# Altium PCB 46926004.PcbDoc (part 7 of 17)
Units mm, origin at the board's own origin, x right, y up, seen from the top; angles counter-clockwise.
Board outline 250 x 200 mm, 6 copper layers (Top Layer, INT1_GND, INT2_SIG, INT3_SIG, INT4_GND, Bottom Layer), stack 1.71 mm thick; 1450 components, 1293 nets, 5656 pads, 2307 vias.
Unrouted connection lines stored in the file: 2.
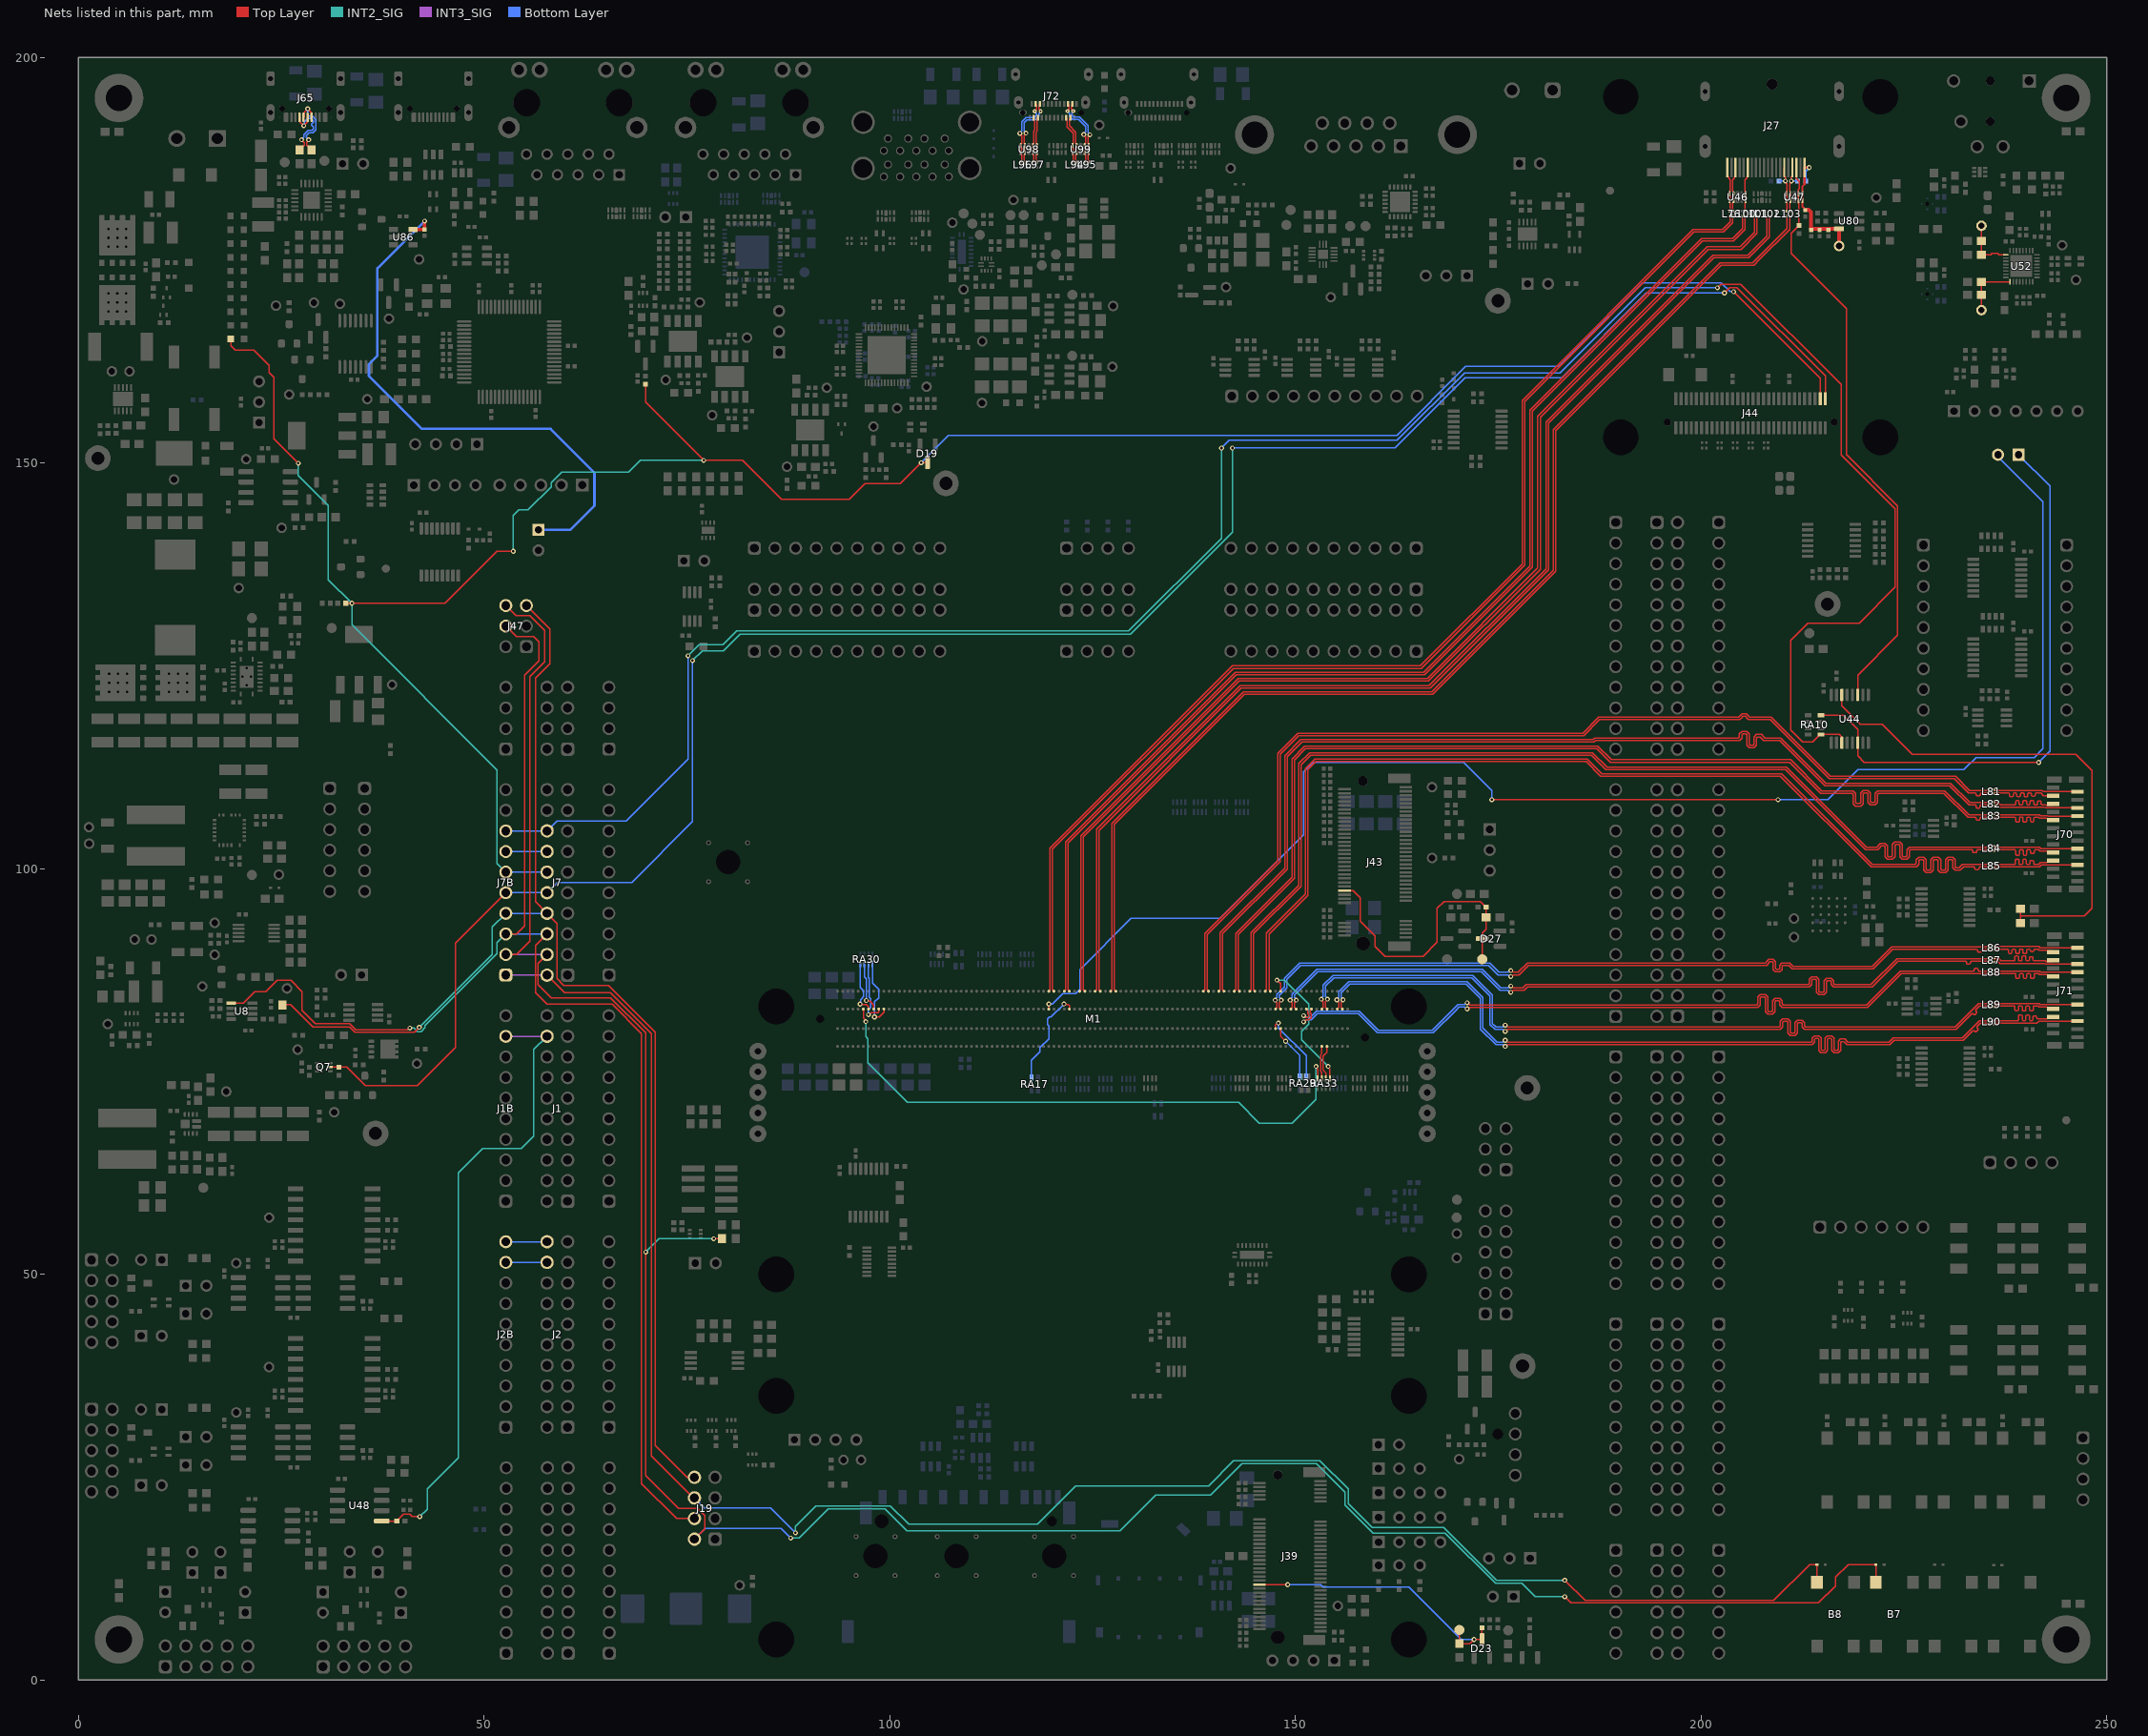
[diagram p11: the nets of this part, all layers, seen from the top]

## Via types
v1: diameter 0.6, hole 0.3, Top Layer to Bottom Layer, tented both sides, 2171 vias
v2: diameter 0.6, hole 0.3, Top Layer to Bottom Layer, 48 vias
v3: diameter 1, hole 0.5, Top Layer to Bottom Layer, tented both sides, 37 vias
v4: diameter 0.5, hole 0.2, Top Layer to Bottom Layer, tented both sides, 34 vias
v5: diameter 0.6, hole 0.3, Top Layer to Bottom Layer, tented bottom, 17 vias

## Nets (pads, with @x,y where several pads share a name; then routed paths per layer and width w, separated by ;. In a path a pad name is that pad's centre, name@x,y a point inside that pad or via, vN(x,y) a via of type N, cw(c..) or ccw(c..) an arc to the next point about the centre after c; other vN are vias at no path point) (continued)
CAN_4_TX: M1.B55 RA17.1 | length 12.1
  Top Layer w0.15: v1(121.476,83.328) 121.563,83.242 122.001,83.242 122.133,83.11 122.133,82.709 M1.B55@122.136,82.706
  Bottom Layer w0.15: RA17.1@117.476,74.27 117.476,76.361 118.526,77.411 118.526,77.955 119.615,79.044 119.615,80.618 119.435,80.797 119.435,81.468 119.704,81.736 119.885,81.736 v1(121.476,83.328)
CAN_4_TX_JMP: J1.18 J1B.9 R50.2 U48.1 | length 78.7
  Top Layer w0.15: U48.1@37.38,19.595 R50.2@39.245,19.595 ; R50.2@39.25,19.6 40.075,20.425 40.864,20.425 41.154,20.135 v1(42.065,20.135)
  INT3_SIG w0.15: J1B.9@52.68,79.34 J1.18@57.76,79.34
  INT2_SIG w0.15: v1(42.065,20.135) 42.99,21.06 42.99,23.55 46.8,27.36 46.8,62.5 49.8,65.5 54.6,65.5 56.125,67.025 56.125,77.705 J1.18@57.76,79.34
CLKRQ_M2B#: D23.3 J39.52 R184.2 R308.2 X62.1 | length 35.4
  Top Layer w0.15: J39.52@145.55,11.775 145.56,11.765 149.04,11.765 v1(149.05,11.755) ; X62.1@170.2,6.175 R308.2@170.2,4.49 171.516,4.49 v1(172.016,4.99) D23.3@172.987,4.99 R184.2@172.987,6.423
  Bottom Layer w0.15: v1(149.05,11.755) 153.095,11.755 153.4,11.45 163.995,11.45 170.455,4.99 v1(172.016,4.99)
CLKRQ_M2M#: D27.3 J43.52 R200.1 R406.2 X66.1 | length 35.4
  Top Layer w0.15: J43.52@156.05,97.3 157.119,97.3 157.975,96.444 157.975,93.544 159.825,91.694 159.825,90.445 161.07,89.2 165.742,89.2 167.475,90.932 167.475,95.112 168.313,95.95 172.816,95.95 R200.1@173.496,95.27 173.496,94.01 R406.2@173.521,93.985 173.521,92.561 173.021,92.061 D27.3@173.021,91.374 X66.1@173.021,88.837
CSI_1_CLK_N: L83.1 M1.A23 | length 126.8
  Top Layer w0.15: M1.A23@142.463,84.9 142.463,84.923 142.63,85.091 142.63,92.008 149.56,98.938 149.56,113.527 151.133,115.1 187.275,115.1 188.95,113.425 211.049,113.425 214.874,109.6 217.575,109.6 218.762,109.6 219.058,109.304 219.058,108.143 219.178,108.023 219.538,108.023 219.658,108.143 219.658,109.336 219.954,109.632 220.562,109.632 220.858,109.336 220.858,108.289 220.978,108.169 221.338,108.169 221.458,108.289 221.458,109.304 221.754,109.6 223.666,109.6 230.051,109.6 233.001,106.65 235.262,106.65 235.287,106.675 235.375,106.675 L83.1@235.45,106.75
CSI_1_CLK_P: L83.2 M1.A22 | length 126.8
  Top Layer w0.15: M1.A22@143.098,84.9 143.098,84.923 142.93,85.091 142.93,91.884 149.86,98.814 149.86,113.403 151.257,114.8 187.151,114.8 188.826,113.125 210.925,113.125 214.75,109.3 217.575,109.3 218.638,109.3 218.758,109.18 218.758,108.019 219.054,107.723 219.662,107.723 219.958,108.019 219.958,109.212 220.078,109.332 220.438,109.332 220.558,109.212 220.558,108.164 220.854,107.869 221.462,107.869 221.758,108.164 221.758,109.18 221.878,109.3 223.666,109.3 229.926,109.3 232.876,106.35 233.208,106.35 233.783,106.35 233.883,106.25 233.883,106.084 233.983,105.984 234.283,105.984 234.383,106.084 234.383,106.25 234.483,106.35 234.93,106.35 235.262,106.35 235.287,106.325 235.375,106.325 L83.2@235.45,106.25
CSI_1_D0_N: L81.1 M1.A29 | length 126.8
  Top Layer w0.15: M1.A29@138.653,84.9 138.653,84.918 138.825,85.091 138.825,92.018 147.8,100.993 147.8,114.229 150.271,116.7 185.4,116.7 187.375,118.675 204.49,118.675 204.653,118.675 204.753,118.775 204.753,118.802 205.029,119.078 205.577,119.078 205.853,118.802 205.853,118.775 205.953,118.675 208.09,118.675 208.649,118.675 215.925,111.399 231.351,111.399 233.1,109.65 235.262,109.65 235.287,109.675 235.375,109.675 L81.1@235.45,109.75
CSI_1_D0_P: L81.2 M1.A28 | length 126.8
  Top Layer w0.15: M1.A28@139.288,84.9 139.288,84.928 139.125,85.091 139.125,91.893 148.1,100.868 148.1,114.104 150.396,116.4 185.524,116.4 187.499,118.375 204.49,118.375 204.777,118.375 205.053,118.651 205.053,118.678 205.153,118.778 205.453,118.778 205.553,118.678 205.553,118.651 205.829,118.375 208.09,118.375 208.525,118.375 215.801,111.099 231.226,111.099 232.976,109.35 233.25,109.35 233.825,109.35 233.925,109.25 233.925,109.081 234.025,108.981 234.325,108.981 234.425,109.081 234.425,109.25 234.525,109.35 234.975,109.35 235.262,109.35 235.287,109.325 235.375,109.325 L81.2@235.45,109.25
CSI_1_D1_N: L82.1 M1.A26 | length 126.8
  Top Layer w0.15: M1.A26@140.558,84.9 140.558,84.923 140.725,85.091 140.725,92.112 148.7,100.087 148.7,113.928 150.672,115.9 186.65,115.9 186.875,116.125 204.444,116.125 204.607,116.125 204.727,116.245 204.727,116.65 205.023,116.945 205.632,116.945 205.927,116.65 205.927,115.319 206.047,115.199 206.407,115.199 206.527,115.319 206.527,116.245 206.823,116.541 207.431,116.541 207.727,116.245 ; 207.727,116.245 207.847,116.125 208.35,116.125 209.824,116.125 215.409,110.54 230.724,110.54 233.114,108.15 235.262,108.15 235.287,108.175 235.375,108.175 L82.1@235.45,108.25
CSI_1_D1_P: L82.2 M1.A25 | length 126.8
  Top Layer w0.15: M1.A25@141.193,84.9 141.193,84.923 141.025,85.091 141.025,91.987 149,99.962 149,113.804 150.796,115.6 186.774,115.6 186.999,115.825 204.444,115.825 204.732,115.825 205.027,116.121 205.027,116.525 205.147,116.645 205.507,116.645 205.627,116.525 205.627,115.194 205.923,114.899 206.532,114.899 206.827,115.194 206.827,116.121 206.947,116.241 207.307,116.241 207.427,116.121 207.723,115.825 208.35,115.825 209.7,115.825 215.285,110.24 230.6,110.24 232.99,107.85 233.219,107.85 233.794,107.85 233.894,107.75 233.894,107.584 233.994,107.484 234.294,107.484 234.394,107.584 234.394,107.75 234.494,107.85 235.244,107.85 235.262,107.85 235.287,107.825 235.375,107.825 L82.2@235.45,107.75
CSI_1_D2_N: L84.1 M1.A20 | length 126.8
  Top Layer w0.15: M1.A20@144.368,84.9 144.368,84.923 144.535,85.091 144.535,92.111 150.396,97.971 150.396,112.961 151.735,114.3 186.6,114.3 188.4,112.5 210.524,112.5 220.374,102.65 220.6,102.65 221.664,102.65 221.784,102.77 221.784,102.827 222.08,103.123 222.688,103.123 222.984,102.827 222.984,101.6 223.104,101.48 223.464,101.48 223.584,101.6 223.584,103.011 223.88,103.307 224.488,103.307 224.784,103.011 224.784,101.6 224.904,101.48 225.264,101.48 225.384,101.6 225.384,102.354 225.68,102.65 225.967,102.65 235.262,102.65 235.287,102.675 235.375,102.675 L84.1@235.45,102.75
CSI_1_D2_P: L84.2 M1.A19 | length 126.8
  Top Layer w0.15: M1.A19@145.003,84.9 145.003,84.923 144.835,85.091 144.835,91.986 150.696,97.847 150.696,112.837 151.859,114 186.476,114 188.276,112.2 210.4,112.2 220.25,102.35 220.6,102.35 221.788,102.35 222.084,102.646 222.084,102.703 222.204,102.823 222.564,102.823 222.684,102.703 222.684,101.476 222.98,101.18 223.588,101.18 223.884,101.476 223.884,102.887 224.004,103.007 224.364,103.007 224.484,102.887 224.484,101.476 224.78,101.18 225.388,101.18 225.684,101.476 225.684,102.23 225.804,102.35 225.967,102.35 232.8,102.35 233.375,102.35 233.475,102.25 233.475,102.084 233.575,101.984 233.875,101.984 233.975,102.084 233.975,102.25 234.075,102.35 234.653,102.35 235.262,102.35 235.287,102.325 235.375,102.325 L84.2@235.45,102.25
CSI_1_D3_N: L85.1 M1.A17 | length 126.8
  Top Layer w0.15: M1.A17@146.273,84.9 146.273,84.923 146.44,85.091 146.44,92.071 151.226,96.857 151.226,112.343 152.383,113.5 185.95,113.5 187.75,111.7 209.899,111.7 221.074,100.525 226.243,100.525 226.406,100.525 226.526,100.645 226.526,101.114 226.821,101.409 227.43,101.409 227.726,101.114 227.726,99.966 227.846,99.846 228.206,99.846 228.326,99.966 228.326,101.114 228.621,101.409 229.23,101.409 229.526,101.114 229.526,99.966 229.646,99.846 230.006,99.846 230.126,99.966 230.126,101.111 230.421,101.407 231.03,101.407 231.326,101.111 231.326,100.229 231.446,100.109 231.806,100.109 231.926,100.229 232.221,100.525 233.028,100.525 235.262,100.525 235.287,100.55 235.375,100.55 L85.1@235.45,100.625
CSI_1_D3_P: L85.2 M1.A16 | length 126.8
  Top Layer w0.15: M1.A16@146.908,84.9 146.908,84.923 146.74,85.091 146.74,91.947 151.526,96.733 151.526,112.219 152.507,113.2 185.826,113.2 187.626,111.4 209.775,111.4 220.95,100.225 226.243,100.225 226.53,100.225 226.826,100.521 226.826,100.989 226.946,101.109 227.306,101.109 227.426,100.989 227.426,99.842 227.721,99.546 228.33,99.546 228.626,99.842 228.626,100.989 228.746,101.109 229.106,101.109 229.226,100.989 229.226,99.842 229.521,99.546 230.13,99.546 230.426,99.842 230.426,100.987 230.546,101.107 230.906,101.107 231.026,100.987 231.026,100.105 231.321,99.809 231.93,99.809 232.226,100.105 232.346,100.225 233.028,100.225 233.054,100.225 233.629,100.225 233.729,100.125 233.729,99.959 233.829,99.859 234.129,99.859 234.229,99.959 234.229,100.125 234.329,100.225 235.1,100.225 235.262,100.225 235.287,100.2 235.375,100.2 L85.2@235.45,100.125
CSI_2_CLK_N: L88.1 M1.B09 | length 96.1
  Top Layer w0.15: v1(151.024,81.882) 151.112,81.882 151.337,81.657 151.541,81.657 151.629,81.745 151.629,82.019 151.52,82.129 151.52,82.509 151.352,82.677 M1.B09@151.352,82.7 ; v1(171.158,83.472) 171.246,83.472 171.246,83.457 171.478,83.225 206.725,83.225 206.888,83.225 207.008,83.345 207.008,84.177 207.304,84.473 207.912,84.473 208.208,84.177 208.208,82.482 208.328,82.362 208.688,82.362 208.808,82.482 208.808,83.717 209.104,84.013 209.712,84.013 210.008,83.717 210.008,83.345 210.128,83.225 210.579,83.225 220.376,83.225 224.541,87.39 233.489,87.39 233.564,87.39 233.664,87.49 233.664,87.595 233.764,87.695 234.064,87.695 234.164,87.595 234.164,87.49 234.264,87.39 235.1,87.39 235.262,87.39 235.287,87.415 235.375,87.415 L88.1@235.45,87.49
  Bottom Layer w0.15: v1(151.024,81.882) 151.112,81.882 151.337,81.657 151.793,81.657 152.572,82.437 157.866,82.437 160.238,80.065 166.863,80.065 169.732,82.934 170.044,83.247 170.845,83.247 171.07,83.472 v1(171.158,83.472)
CSI_2_CLK_P: L88.2 M1.B08 | length 96.2
  Top Layer w0.15: v1(151.024,81.132) 151.112,81.132 151.337,81.357 151.666,81.357 151.929,81.621 151.929,82.144 151.82,82.253 151.82,82.509 151.987,82.677 M1.B08@151.987,82.7 ; v1(171.158,82.722) 171.267,82.722 171.471,82.925 206.725,82.925 207.012,82.925 207.308,83.221 207.308,84.053 207.428,84.173 207.788,84.173 207.908,84.053 207.908,82.357 208.204,82.062 208.812,82.062 209.108,82.357 209.108,83.593 209.228,83.713 209.588,83.713 209.708,83.593 209.708,83.221 210.004,82.925 210.579,82.925 220.5,82.925 224.665,87.09 235.262,87.09 235.287,87.065 235.375,87.065 L88.2@235.45,86.99
  Bottom Layer w0.15: v1(151.024,81.132) 151.112,81.132 151.337,81.357 151.917,81.357 152.696,82.137 157.742,82.137 160.113,79.765 166.987,79.765 169.856,82.634 170.169,82.947 170.845,82.947 171.07,82.722 v1(171.158,82.722)
CSI_2_D0_N: L86.1 M1.B15 | length 96.6
  Top Layer w0.15: v1(147.5,83.8) 147.5,83.697 147.71,83.487 147.71,82.891 147.542,82.723 M1.B15@147.542,82.7 ; v1(176.538,87.45) 176.626,87.45 176.851,87.225 177.451,87.225 178.596,88.37 207.804,88.37 207.967,88.37 208.067,88.47 208.067,88.566 208.343,88.842 208.892,88.842 209.167,88.566 209.167,87.68 209.267,87.58 209.567,87.58 209.667,87.68 209.667,88.094 209.943,88.37 210.637,88.37 210.8,88.37 210.924,88.37 211.324,87.97 221.09,87.97 223.51,90.39 235.262,90.39 235.287,90.415 235.375,90.415 L86.1@235.45,90.49
  Bottom Layer w0.15: v1(147.5,83.8) 147.5,83.888 147.725,84.113 147.725,84.49 148.669,85.434 148.669,86.499 150.535,88.365 173.977,88.365 174.21,88.132 174.21,88.11 175.095,87.225 176.225,87.225 176.45,87.45 v1(176.538,87.45) 176.435,87.45 176.225,87.24
CSI_2_D0_P: L86.2 M1.B14 | length 96.6
  Top Layer w0.15: M1.B14@148.177,82.7 148.177,82.723 148.01,82.891 148.01,83.472 148.25,83.712 v1(148.25,83.8) ; v1(176.538,86.7) 176.626,86.7 176.851,86.925 177.575,86.925 178.72,88.07 207.804,88.07 208.092,88.07 208.367,88.346 208.367,88.442 208.467,88.542 208.767,88.542 208.867,88.442 208.867,87.555 209.143,87.28 209.692,87.28 209.967,87.555 209.967,87.97 210.067,88.07 210.637,88.07 210.8,88.07 211.2,87.67 221.214,87.67 223.634,90.09 233.409,90.09 233.984,90.09 234.084,89.99 234.084,89.825 234.184,89.725 234.484,89.725 234.584,89.825 234.584,89.99 234.684,90.09 235.157,90.09 235.262,90.09 235.287,90.065 235.375,90.065 L86.2@235.45,89.99
  Bottom Layer w0.15: v1(148.25,83.8) 148.25,83.888 148.025,84.113 148.025,84.366 148.969,85.31 148.969,86.374 150.66,88.065 173.81,88.065 173.977,87.898 173.998,87.898 174.971,86.925 176.225,86.925 176.45,86.7 v1(176.538,86.7) 176.435,86.7 176.225,86.91
CSI_2_D1_N: L87.1 M1.B12 | length 96.6
  Top Layer w0.15: v1(149.35,83.8) 149.35,83.712 149.361,83.712 149.586,83.487 149.586,82.891 149.447,82.752 M1.B12@149.447,82.7 ; v1(176.538,85.524) 176.626,85.524 176.851,85.299 177.252,85.299 ; L87.1@235.45,88.99 235.375,88.915 235.287,88.915 235.262,88.89 224.122,88.89 220.944,85.712 216.759,85.712 216.456,85.712 216.336,85.832 216.336,86.183 216.04,86.478 215.432,86.478 215.136,86.183 215.136,84.912 215.016,84.792 214.656,84.792 214.536,84.912 214.536,86.353 214.24,86.648 213.632,86.648 213.336,86.353 213.336,85.832 213.216,85.712 213.053,85.712 178.462,85.712 178.05,85.3 177.253,85.3 ; 177.252,85.299 177.253,85.3
  Bottom Layer w0.15: v1(149.35,83.8) 149.35,83.888 149.575,84.113 149.575,84.568 152.622,87.615 173.035,87.615 175.351,85.299 176.225,85.299 176.45,85.524 v1(176.538,85.524) 176.435,85.524 176.225,85.314
CSI_2_D1_P: L87.2 M1.B11 | length 96.6
  Top Layer w0.15: M1.B11@150.082,82.7 150.082,82.734 149.886,82.93 149.886,83.487 150.1,83.702 v1(150.1,83.8) ; v1(176.538,84.774) 176.626,84.774 176.851,84.999 177.376,84.999 177.377,85 178.174,85 178.586,85.412 213.053,85.412 213.34,85.412 213.636,85.708 213.636,86.228 213.756,86.348 214.116,86.348 214.236,86.228 214.236,84.788 214.532,84.492 215.14,84.492 215.436,84.788 215.436,86.058 215.556,86.178 215.916,86.178 216.036,86.058 216.036,85.708 216.332,85.412 216.759,85.412 221.068,85.412 224.246,88.59 232.024,88.59 232.599,88.59 232.699,88.49 232.699,88.336 232.799,88.236 233.099,88.236 233.199,88.336 233.199,88.49 233.299,88.59 233.781,88.59 235.262,88.59 235.287,88.565 235.375,88.565 L87.2@235.45,88.49
  Bottom Layer w0.15: v1(150.1,83.8) 150.1,83.888 149.875,84.113 149.875,84.444 152.746,87.315 172.911,87.315 175.227,84.999 176.225,84.999 176.45,84.774 v1(176.538,84.774) 176.435,84.774 176.225,84.984
CSI_2_D2_N: L89.1 M1.B06 | length 96.2
  Top Layer w0.15: v1(153.194,83.922) 153.194,83.835 153.419,83.61 153.419,83.231 153.425,83.225 153.425,82.891 153.257,82.723 M1.B06@153.257,82.7 ; v1(175.847,80.705) 175.935,80.705 176.165,80.475 209.49,80.475 209.653,80.475 209.773,80.595 209.773,81.187 210.069,81.483 210.677,81.483 210.973,81.187 210.973,79.831 211.093,79.711 211.453,79.711 211.573,79.831 211.573,81.042 211.869,81.338 212.477,81.338 212.773,81.042 212.773,80.595 212.893,80.475 213.42,80.475 231.29,80.475 234.205,83.39 235.262,83.39 235.287,83.415 235.375,83.415 L89.1@235.45,83.49
  Bottom Layer w0.15: v1(153.194,83.922) 153.194,84.01 153.419,84.235 153.419,85.653 154.621,86.855 171.882,86.855 174.291,84.446 174.291,80.907 174.718,80.48 175.534,80.48 175.759,80.705 v1(175.847,80.705)
CSI_2_D2_P: L89.2 M1.B05 | length 96.2
  Top Layer w0.15: M1.B05@153.892,82.7 153.892,82.723 153.725,82.891 153.725,83.35 153.719,83.355 153.719,83.61 153.944,83.835 v1(153.944,83.922) ; v1(175.847,79.955) 175.94,79.955 176.16,80.175 209.49,80.175 209.777,80.175 210.073,80.471 210.073,81.063 210.193,81.183 210.553,81.183 210.673,81.063 210.673,79.707 210.969,79.411 211.577,79.411 211.873,79.707 211.873,80.918 211.993,81.038 212.353,81.038 212.473,80.918 212.473,80.471 212.769,80.175 213.42,80.175 231.414,80.175 232.966,81.727 233.373,82.134 233.514,82.134 233.633,82.015 233.774,82.015 233.986,82.227 233.986,82.369 233.868,82.487 233.868,82.629 234.084,82.845 234.329,83.09 235.262,83.09 235.287,83.065 235.375,83.065 L89.2@235.45,82.99
  Bottom Layer w0.15: v1(153.944,83.922) 153.944,84.01 153.719,84.235 153.719,85.529 154.745,86.555 171.757,86.555 173.991,84.322 173.991,80.783 174.593,80.18 175.534,80.18 175.759,79.955 v1(175.847,79.955)
CSI_2_D3_N: L90.1 M1.B03 | length 96.2
  Top Layer w0.15: v1(155.107,83.843) 155.107,83.755 155.332,83.53 155.332,83.229 155.33,83.227 155.33,82.891 155.162,82.723 M1.B03@155.162,82.7 ; v1(175.847,78.85) 175.935,78.85 176.16,78.625 213.428,78.625 213.591,78.625 213.691,78.725 213.691,79.129 213.967,79.405 214.515,79.405 214.791,79.129 214.791,77.71 214.891,77.61 215.191,77.61 215.291,77.71 215.291,79.129 215.567,79.405 216.115,79.405 216.391,79.129 216.391,77.738 216.491,77.638 216.791,77.638 216.891,77.738 216.891,78.725 217.167,79.001 217.715,79.001 217.991,78.725 218.091,78.625 219.416,78.625 223.143,78.625 223.668,79.15 232.185,79.15 234.3,81.265 235.262,81.265 235.287,81.29 235.375,81.29 L90.1@235.45,81.365
  Bottom Layer w0.15: v1(155.107,83.843) 155.107,83.931 155.332,84.156 155.332,84.831 156.591,86.09 171.152,86.09 173.111,84.13 173.111,80.347 174.833,78.625 175.534,78.625 175.759,78.85 v1(175.847,78.85)
CSI_2_D3_P: L90.2 M1.B02 | length 96.2
  Top Layer w0.15: M1.B02@155.797,82.7 155.797,82.723 155.63,82.891 155.63,83.102 155.632,83.105 155.632,83.53 155.857,83.755 v1(155.857,83.843) ; v1(175.847,78.1) 175.935,78.1 176.16,78.325 213.428,78.325 213.715,78.325 213.991,78.601 213.991,79.005 214.091,79.105 214.391,79.105 214.491,79.005 214.491,77.586 214.767,77.31 215.315,77.31 215.591,77.586 215.591,79.005 215.691,79.105 215.991,79.105 216.091,79.005 216.091,77.614 216.367,77.338 216.915,77.338 217.191,77.614 217.191,78.601 217.291,78.701 217.591,78.701 217.691,78.601 217.967,78.325 219.416,78.325 223.267,78.325 223.792,78.85 232.309,78.85 233.093,79.634 233.5,80.04 233.641,80.04 233.758,79.923 233.9,79.923 234.112,80.135 234.112,80.277 233.995,80.394 233.995,80.535 234.389,80.93 234.424,80.965 235.262,80.965 235.287,80.94 235.375,80.94 L90.2@235.45,80.865
  Bottom Layer w0.15: v1(155.857,83.843) 155.857,83.931 155.632,84.156 155.632,84.707 156.715,85.79 171.028,85.79 172.811,84.006 172.811,80.222 174.709,78.325 175.534,78.325 175.759,78.1 v1(175.847,78.1)
CSI_C1_CLK_N: J70.8 L83.4 | length 10.4
  Top Layer w0.15: L83.4@236.1,106.75 236.175,106.675 236.263,106.675 236.288,106.65 239.313,106.65 241.688,106.65 241.833,106.505 242.761,106.505 242.776,106.49 J70.8@246.4,106.49
CSI_C1_CLK_P: J70.9 L83.3 | length 10.4
  Top Layer w0.15: L83.3@236.1,106.25 236.175,106.325 236.263,106.325 236.288,106.35 238.163,106.35 238.688,106.35 238.778,106.26 238.778,105.852 238.868,105.762 239.138,105.762 239.228,105.852 239.228,106.26 239.318,106.35 239.588,106.35 239.678,106.26 239.678,105.852 239.768,105.762 240.038,105.762 240.128,105.852 240.128,106.26 240.218,106.35 240.488,106.35 240.578,106.26 240.578,105.855 240.668,105.765 240.938,105.765 241.028,105.855 241.028,106.26 241.118,106.35 241.368,106.35 241.564,106.35 241.709,106.205 242.637,106.205 242.667,106.175 243.215,106.175 J70.9@243.4,105.99
CSI_C1_D0_N: J70.2 L81.4 | length 10.4
  Top Layer w0.15: L81.4@236.1,109.75 236.125,109.75 236.24,109.635 242.015,109.635 242.16,109.49 J70.2@246.4,109.49
CSI_C1_D0_P: J70.3 L81.3 | length 10.4
  Top Layer w0.15: L81.3@236.1,109.25 236.125,109.25 236.2,109.325 236.278,109.325 236.288,109.335 237.4,109.335 237.925,109.335 238.015,109.245 238.015,108.94 238.105,108.85 238.375,108.85 238.465,108.94 238.465,109.245 238.555,109.335 238.825,109.335 238.915,109.245 238.915,108.94 239.005,108.85 239.275,108.85 239.365,108.94 239.365,109.245 239.455,109.335 239.725,109.335 239.815,109.245 239.815,108.94 239.905,108.85 240.175,108.85 240.265,108.94 240.265,109.245 240.355,109.335 240.625,109.335 240.715,109.245 240.715,108.993 240.805,108.903 241.075,108.903 241.165,108.993 241.165,109.245 241.255,109.335 241.668,109.335 241.865,109.335 242.21,108.99 J70.3@243.4,108.99
CSI_C1_D1_N: J70.5 L82.4 | length 10.5
  Top Layer w0.15: L82.4@236.1,108.25 236.175,108.175 236.263,108.175 236.288,108.15 236.624,108.15 236.874,107.9 238.6,107.9 238.675,107.9 238.765,107.99 238.765,108.291 238.855,108.381 239.125,108.381 239.215,108.291 239.215,107.99 239.305,107.9 239.575,107.9 239.665,107.99 239.665,108.291 239.755,108.381 240.025,108.381 240.115,108.291 240.115,107.99 240.205,107.9 240.475,107.9 240.565,107.99 240.565,108.291 240.655,108.381 240.925,108.381 241.015,108.291 241.015,107.99 241.105,107.9 241.375,107.9 241.465,107.99 241.465,108.279 241.555,108.369 241.825,108.369 241.915,108.279 241.915,107.99 242.005,107.9 242.367,107.9 242.422,107.9 242.513,107.809 243.219,107.809 J70.5@243.4,107.99
CSI_C1_D1_P: J70.6 L82.3 | length 10.5
  Top Layer w0.15: L82.3@236.1,107.75 236.175,107.825 236.263,107.825 236.288,107.85 236.5,107.85 236.75,107.6 241.419,107.6 242.297,107.6 242.392,107.505 246.385,107.505 J70.6@246.4,107.49
CSI_C1_D2_N: J70.16 L84.4 | length 10.4
  Top Layer w0.15: L84.4@236.1,102.75 236.175,102.675 236.263,102.675 236.288,102.65 241.733,102.65 241.893,102.49 J70.16@246.4,102.49
CSI_C1_D2_P: J70.17 L84.3 | length 10.5
  Top Layer w0.15: L84.3@236.1,102.25 236.175,102.325 236.263,102.325 236.288,102.35 238.185,102.35 238.71,102.35 238.8,102.26 238.8,101.764 238.89,101.674 239.16,101.674 239.25,101.764 239.25,102.26 239.34,102.35 239.61,102.35 239.7,102.26 239.7,101.764 239.79,101.674 240.06,101.674 240.15,101.764 240.15,102.26 240.24,102.35 240.51,102.35 240.6,102.26 240.6,101.989 240.69,101.899 240.96,101.899 241.05,101.989 241.05,102.26 241.14,102.35 241.609,102.35 241.769,102.19 242.652,102.19 242.667,102.175 242.877,102.175 243.215,102.175 J70.17@243.4,101.99
CSI_C1_D3_N: J70.19 L85.4 | length 10.4
  Top Layer w0.15: L85.4@236.1,100.625 236.175,100.55 236.263,100.55 236.288,100.525 238.569,100.525 238.644,100.525 238.734,100.615 238.734,101.07 238.824,101.16 239.094,101.16 239.184,101.07 239.184,100.615 239.274,100.525 239.544,100.525 239.634,100.615 239.634,101.07 239.724,101.16 239.994,101.16 240.084,101.07 240.084,100.615 240.174,100.525 240.444,100.525 240.534,100.615 240.534,100.923 240.624,101.013 240.894,101.013 240.984,100.923 240.984,100.615 241.074,100.525 241.569,100.525 241.819,100.775 242.206,100.775 242.637,100.775 242.667,100.805 243.215,100.805 J70.19@243.4,100.99
CSI_C1_D3_P: J70.20 L85.3 | length 10.5
  Top Layer w0.15: L85.3@236.1,100.125 236.175,100.2 236.263,100.2 236.288,100.225 241.694,100.225 241.944,100.475 243.613,100.475 244.213,100.475 246.385,100.475 J70.20@246.4,100.49
CSI_C2_CLK_N: J71.8 L88.4 | length 10.4
  Top Layer w0.15: L88.4@236.1,87.49 236.175,87.415 236.263,87.415 236.288,87.39 241.7,87.39 241.845,87.245 246.385,87.245 J71.8@246.4,87.23
CSI_C2_CLK_P: J71.9 L88.3 | length 10.4
  Top Layer w0.15: L88.3@236.1,86.99 236.175,87.065 236.263,87.065 236.288,87.09 238.185,87.09 238.71,87.09 238.8,87 238.8,86.59 238.89,86.5 239.16,86.5 239.25,86.59 239.25,87 239.34,87.09 239.61,87.09 239.7,87 239.7,86.59 239.79,86.5 240.06,86.5 240.15,86.59 240.15,87 240.24,87.09 240.51,87.09 240.6,87 240.6,86.59 240.69,86.5 240.96,86.5 241.05,86.59 241.05,87 241.14,87.09 241.487,87.09 241.576,87.09 241.721,86.945 242.637,86.945 242.667,86.915 243.215,86.915 J71.9@243.4,86.73
CSI_C2_D0_N: J71.2 L86.4 | length 10.4
  Top Layer w0.15: L86.4@236.1,90.49 236.175,90.415 236.27,90.415 236.288,90.398 241.626,90.398 241.794,90.23 J71.2@246.4,90.23
CSI_C2_D0_P: J71.3 L86.3 | length 10.4
  Top Layer w0.15: L86.3@236.1,89.99 236.175,90.065 237.263,90.065 237.788,90.065 237.878,89.975 237.878,89.65 237.968,89.56 238.238,89.56 238.328,89.65 238.328,90.008 238.418,90.098 238.688,90.098 238.778,90.008 238.778,89.65 238.868,89.56 239.138,89.56 239.228,89.65 239.228,90.008 239.318,90.098 239.588,90.098 239.678,90.008 239.678,89.65 239.768,89.56 240.038,89.56 240.128,89.65 240.128,90.008 240.218,90.098 240.488,90.098 240.578,90.008 240.578,89.89 240.668,89.8 240.938,89.8 241.028,89.89 241.028,89.975 241.118,90.065 241.534,90.065 241.669,89.93 242.24,89.93 242.637,89.93 242.652,89.915 243.215,89.915 J71.3@243.4,89.73
CSI_C2_D1_N: J71.5 L87.4 | length 10.5
  Top Layer w0.15: L87.4@236.1,88.99 236.175,88.915 236.263,88.915 236.288,88.89 236.694,88.89 236.948,88.636 238.499,88.636 238.574,88.636 238.664,88.726 238.664,89.17 238.754,89.26 239.024,89.26 239.114,89.17 239.114,88.726 239.204,88.636 239.474,88.636 239.564,88.726 239.564,89.17 239.654,89.26 239.924,89.26 240.014,89.17 240.014,88.726 240.104,88.636 240.374,88.636 240.464,88.726 240.464,89.061 240.554,89.151 240.824,89.151 240.914,89.061 240.914,88.726 241.004,88.636 241.769,88.636 242.426,88.636 242.513,88.549 243.219,88.549 J71.5@243.4,88.73
CSI_C2_D1_P: J71.6 L87.3 | length 10.5
  Top Layer w0.15: L87.3@236.1,88.49 236.175,88.565 236.263,88.565 236.288,88.59 236.57,88.59 236.824,88.336 241.079,88.336 242.302,88.336 242.392,88.245 246.385,88.245 J71.6@246.4,88.23
CSI_C2_D2_N: J71.16 L89.4 | length 10.4
  Top Layer w0.15: L89.4@236.1,83.49 236.175,83.415 236.263,83.415 236.288,83.39 241.639,83.39 241.784,83.245 244.213,83.245 244.228,83.23 J71.16@246.4,83.23
CSI_C2_D2_P: J71.17 L89.3 | length 10.5
  Top Layer w0.15: L89.3@236.1,82.99 236.175,83.065 236.263,83.065 236.288,83.09 238.06,83.09 238.585,83.09 238.675,83 238.675,82.573 238.765,82.483 239.035,82.483 239.125,82.573 239.125,83 239.215,83.09 239.485,83.09 239.575,83 239.575,82.573 239.665,82.483 239.935,82.483 240.025,82.573 240.025,83 240.115,83.09 240.385,83.09 240.475,83 240.475,82.588 240.565,82.498 240.835,82.498 240.925,82.588 240.925,83 241.015,83.09 241.114,83.09 241.514,83.09 241.659,82.945 242.637,82.945 242.667,82.915 243.215,82.915 J71.17@243.4,82.73
CSI_C2_D3_N: J71.19 L90.4 | length 10.5
  Top Layer w0.15: L90.4@236.1,81.365 236.175,81.29 236.263,81.29 236.288,81.265 238.955,81.265 239.03,81.265 239.12,81.355 239.12,81.882 239.21,81.972 239.48,81.972 239.57,81.882 239.57,81.355 239.66,81.265 239.93,81.265 240.02,81.355 240.02,81.882 240.11,81.972 240.38,81.972 240.47,81.882 240.47,81.355 240.56,81.265 240.83,81.265 240.92,81.355 240.92,81.738 241.01,81.828 241.28,81.828 241.37,81.738 241.37,81.605 241.46,81.515 241.882,81.515 242.637,81.515 242.667,81.545 243.215,81.545 J71.19@243.4,81.73
CSI_C2_D3_P: J71.20 L90.3 | length 10.5
  Top Layer w0.15: L90.3@236.1,80.865 236.175,80.94 236.263,80.94 236.288,80.965 241.384,80.965 241.634,81.215 243.613,81.215 244.213,81.215 246.385,81.215 J71.20@246.4,81.23
CTRL_FORCE_OFF_MOCI#: M1.B94 RA30.4 | length 6.8
  Top Layer w0.15: v1(96.34,83.314) 96.426,83.227 97.15,83.227 97.377,83.001 M1.B94@97.377,82.7
  Bottom Layer w0.15: v1(96.34,83.314) 96.426,83.4 96.426,83.822 96.657,84.053 96.657,84.114 96.775,84.233 96.775,84.945 96.375,85.345 RA30.4@96.375,88.25
CTRL_FORCE_OFF_MOCI#JMP: J7.8 J7B.4 J19.8 J47.5 R54.2 | length 163.3
  Top Layer w0.15: R54.2@25.175,83.25 26.143,83.25 28.898,80.495 33.422,80.495 34.076,79.841 41.405,79.841 v1(42.016,80.452) ; J47.5@55.22,132.44 58.125,129.535 58.125,125.287 56.325,123.487 56.325,95.935 J7.8@57.76,94.5 58.995,93.265 58.995,86.458 59.822,85.632 65.318,85.632 71.1,79.85 71.1,28.915 75.03,24.985 J19.8@75.929,24.985
  INT2_SIG w0.15: v1(42.016,80.452) 51.014,89.45 51.014,92.834 J7B.4@52.68,94.5
  Bottom Layer w0.15: J7B.4@52.68,94.5 J7.8@57.76,94.5
CTRL_MCLK_3V: R359.2 R367.2 U44.14 | length 63.8
  Top Layer w0.15: U44.14@217.35,121.725 217.35,120.075 219.6,117.825 222.3,117.825 226.025,114.1 246.2,114.1 248.2,112.1 248.2,95.125 247.238,94.163 239.375,94.163 ; R367.2@239.375,93.275 239.375,94.163 ; R359.2@239.375,95.05 239.375,94.163
CTRL_MCLK_JMP: J7.16 J7B.8 RA10.1 U44.3 | length 274.3
  Top Layer w0.15: v1(202.008,171.61) 202.456,172.058 204.862,172.058 217.25,159.67 217.25,150.996 223.9,144.346 223.9,134.7 219.486,130.286 213.183,130.286 211.049,128.152 211.049,117.093 212.492,115.65 213.75,115.65 214.625,116.525 RA10.1@214.775,116.525 214.8,116.55 217.011,116.55 217.35,116.211 U44.3@217.35,115.525 U44.3@217.35,115.225
  INT2_SIG w0.15: v1(75.14,126.244) 76.505,127.61 79.429,127.61 81.13,129.311 129.465,129.311 140.889,140.735 v1(140.889,151.85)
  Bottom Layer w0.15: J7B.8@52.68,104.66 J7.16@57.76,104.66 59,105.9 67.5,105.9 75.14,113.54 v1(75.14,126.244) ; v1(140.889,151.85) 141.832,152.794 162.518,152.794 170.842,161.118 182.61,161.118 193.102,171.61 v1(202.008,171.61)
CTRL_MCLK_MOCI: M1.A14 RA33.1 | length 17.7
  Top Layer w0.15: v1(147.72,86.271) 148.178,85.813 M1.A14@148.178,84.9 ; v1(154.034,75.624) 154.034,75.502 154.247,75.29 RA33.1@154.247,74.148
  INT2_SIG w0.15: v1(147.72,86.271) 148.654,86.271 151.628,83.297 151.628,80.854 150.735,79.961 150.735,78.924 v1(154.034,75.624)
CTRL_PWR_BTN_MICO#: M1.B93 RA30.3 | length 6.2
  Top Layer w0.15: v1(97.099,83.752) 97.185,83.666 97.566,83.666 98.012,83.221 M1.B93@98.012,82.7
  Bottom Layer w0.15: RA30.3@96.875,88.25 96.875,86.657 97.099,86.433 v1(97.099,83.752)
CTRL_PWR_BTN_MICO#JMP: J7.6 J7B.3 J19.4 J47.4 U8.5 | length 180.3
  Top Layer w0.15: U8.5@18.835,83.425 20.312,83.425 21.756,84.869 23.112,84.869 24.482,86.239 26.197,86.239 27.582,84.854 27.582,82.531 29.213,80.9 33.442,80.9 34.2,80.141 40.537,80.141 40.762,80.366 v1(40.85,80.366) ; J7B.3@52.68,91.96 54.01,91.96 55,92.95 55,123.867 56.765,125.632 56.765,127.96 56.125,128.6 53.98,128.6 J47.4@52.68,129.9 ; J7.6@57.76,91.96 56.325,90.525 56.325,84.752 57.777,83.3 65.8,83.3 69.411,79.689 69.411,24.231 73.737,19.905 J19.4@75.929,19.905
  INT2_SIG w0.15: v1(40.85,80.366) 40.866,80.351 41.375,80.351 41.799,79.927 42.234,79.927 42.725,80.419 42.725,80.675 51.614,89.564 51.614,90.894 J7B.3@52.68,91.96
  Bottom Layer w0.15: J7B.3@52.68,91.96 J7.6@57.76,91.96
CTRL_PWR_EN_MOCI: M1.B95 RA33.4 | length 72
  Top Layer w0.15: M1.B95@96.742,82.7 96.742,81.588 97.049,81.281 v1(97.049,81.159) ; v1(152.534,75.624) 152.534,75.502 152.747,75.29 RA33.4@152.747,74.148
  INT2_SIG w0.15: v1(97.049,81.159) 97.049,79.301 97.313,79.037 97.313,76.076 102.189,71.2 142.988,71.2 145.553,68.636 149.6,68.636 152.534,71.57 v1(152.534,75.624)
CTRL_PWR_EN_MOCI_JMP: J7.10 J7B.5 J44.59 Q7.2 R56.1 | length 258.5
  Top Layer w0.15: Q7.2@31.04,75.55 R56.1@32.125,75.55 32.134,75.559 33.098,75.559 35.381,73.275 41.779,73.275 46.5,77.996 46.5,90.86 J7B.5@52.68,97.04 ; v1(202.872,170.975) 203.545,171.648 204.409,171.648 215.307,160.75 J44.59@215.307,157.95
  INT2_SIG w0.15: v1(75.692,125.656) 76.91,126.874 79.509,126.874 81.535,128.9 129.643,128.9 142.222,141.48 v1(142.222,151.85)
  Bottom Layer w0.15: J7B.5@52.68,97.04 J7.10@57.76,97.04 59.03,98.31 68.21,98.31 75.692,105.792 v1(75.692,125.656) ; v1(142.222,151.85) 162.25,151.85 170.944,160.544 182.835,160.544 193.267,170.975 v1(202.872,170.975)
CTRL_RECOVERY_MICO#: M1.B91 RA30.1 | length 8.8
  Top Layer w0.15: v1(98.125,81.722) 98.704,81.722 99.282,82.3 M1.B91@99.282,82.7
  Bottom Layer w0.15: RA30.1@97.875,88.25 97.875,85.883 98.625,85.133 98.625,84.096 98.125,83.596 v1(98.125,81.722)
CTRL_RECOVERY_MICO#JMP: B8.3 D35.1 J7.2 J7B.1 J19.6 | length 238.8
  Top Layer w0.15: J7.2@57.76,86.88 59.94,84.7 65.6,84.7 70.625,79.675 70.625,27.639 75.819,22.445 J19.6@75.929,22.445 ; v1(183.2,12.3) 185.7,9.8 208.955,9.8 213.38,14.225 214.3,14.225 D35.1@214.295,14.22 214.289,14.214 B8.3@214.289,12.037
  INT3_SIG w0.15: J7B.1@52.68,86.88 J7.2@57.76,86.88
  INT2_SIG w0.15: v1(88.374,18.134) 88.374,18.943 90.901,21.47 92.163,21.47 93.017,21.47 100.085,21.47 102.355,19.2 118.2,19.2 122.925,23.925 139.298,23.925 142.387,27.015 153.024,27.015 156.5,23.539 156.5,21.768 159.468,18.8 168.277,18.8 174.777,12.3 v1(183.2,12.3)
  Bottom Layer w0.15: J19.6@75.929,22.445 77.174,21.2 85.308,21.2 v1(88.374,18.134)
CTRL_RESET_MICO#: M1.B92 RA30.2 | length 8.2
  Top Layer w0.15: v1(97.378,82.011) 97.499,82.011 97.735,82.247 98.542,82.247 98.647,82.352 M1.B92@98.647,82.7
  Bottom Layer w0.15: RA30.2@97.375,88.25 97.375,86.582 97.454,86.503 97.454,84.14 97.624,83.97 97.624,82.918 97.378,82.672 v1(97.378,82.011)
CTRL_RESET_MICO#JMP: B7.3 D33.1 J7.4 J7B.2 J19.2 J47.6 R464.1 | length 316.7
  Top Layer w0.15: J7B.2@52.68,89.42 54.01,89.42 55.658,91.068 55.658,123.681 57.45,125.473 57.45,129.402 55.658,131.195 53.925,131.195 J47.6@52.68,132.44 ; J7.4@57.76,89.42 56.65,88.31 56.65,85.725 58.275,84.1 65.6,84.1 69.936,79.764 v1(69.936,52.75) 69.936,25.189 73.95,21.175 76.3,21.175 77.2,20.275 77.2,18.636 J19.2@75.929,17.365 ; v1(78.3,54.4) R464.1@79.325,54.4 ; v1(183.2,10.274) 183.974,9.5 214.471,9.5 216.575,11.604 216.575,12.675 218.125,14.225 221.55,14.225 D33.1@221.539,14.214 B7.3@221.539,12.037
  INT3_SIG w0.15: J7B.2@52.68,89.42 J7.4@57.76,89.42
  INT2_SIG w0.15: v1(69.936,52.75) 71.586,54.4 v1(78.3,54.4) ; v1(87.786,17.49) 88.815,17.49 92.065,20.74 92.425,21.1 92.962,21.1 99.425,21.1 102.125,18.4 128.4,18.4 132.8,22.8 139.537,22.8 143.437,26.7 152.581,26.7 156.125,23.156 156.125,21.55 159.573,18.102 168.453,18.102 174.655,11.9 177.9,11.9 179.526,10.274 v1(183.2,10.274)
  Bottom Layer w0.15: J19.2@75.929,17.365 77.264,18.7 86.576,18.7 v1(87.786,17.49)
CTRL_RESET_MOCI#: M1.D05 RA33.2 | length 4.3
  Top Layer w0.18: RA33.2@153.747,74.148 153.747,74.833 153.419,75.161 153.419,76.914 153.892,77.387 M1.D05@153.892,78.1
CTRL_RESET_MOCI#JMP: D19.3 D34.2 J7.12 J7B.6 J44.57 R358.2 R400.2 | length 311.7
  Top Layer w0.15: D34.2@18.775,165.3 18.775,164.478 19.353,163.9 21.618,163.9 23.495,162.023 23.495,161.184 24.081,160.598 24.081,152.968 27.074,149.975 v1(27.112,149.975) ; R358.2@32.961,132.722 v1(33.7,132.722) 45.172,132.722 51.575,139.125 v1(53.605,139.125) ; R400.2@69.876,159.724 69.9,159.7 69.9,157.506 v1(77.071,150.335) 81.875,150.335 86.66,145.55 95.025,145.55 96.934,147.46 101.294,147.46 v1(103.882,150.049) D19.3@104.664,150.049 ; v1(204.003,171.123) 214.672,160.453 J44.57@214.672,157.95
  INT2_SIG w0.15: v1(27.112,149.975) 27.112,148.472 30.796,144.788 30.796,135.625 v1(33.7,132.722) 33.7,130.071 51.609,112.163 51.609,100.651 J7B.6@52.68,99.58 ; v1(53.605,139.125) 53.605,143.529 54.291,144.215 55.431,144.215 58.268,147.052 58.268,147.593 59.575,148.9 67.828,148.9 69.263,150.335 v1(77.071,150.335)
  Bottom Layer w0.15: J7B.6@52.68,99.58 J7.12@57.76,99.58 ; v1(103.882,150.049) 107.234,153.4 162.5,153.4 171,161.9 182.469,161.9 192.787,172.218 202.47,172.218 203.565,171.123 v1(204.003,171.123)
CTRL_TAMPER0: M1.C14 RA29.1 | length 6.9
  Top Layer w0.18: M1.C14@148.177,80.3 148.177,79.348 v1(148.797,78.728)
  Bottom Layer w0.18: v1(148.797,78.728) 150.525,77 RA29.1@150.525,74.35
CTRL_TAMPER0_JMP: J2.20 J2B.10 | length 5.1
  Bottom Layer w0.15: J2B.10@52.68,54.02 J2.20@57.76,54.02
CTRL_TAMPER1: M1.C15 RA29.2 | length 8.9
  Top Layer w0.15: M1.C15@147.542,80.3 147.542,80.725 147.8,80.983 v1(147.902,80.983)
  Bottom Layer w0.15: v1(147.902,80.983) 147.902,80.365 151.325,76.942 RA29.2@151.325,74.35
CTRL_TAMPER1_JMP: J2.18 J2B.9 | length 5.1
  Bottom Layer w0.15: J2B.9@52.68,51.48 J2.18@57.76,51.48
CTRL_WAKE1_MICO#: M1.D06 RA33.3 | length 4.1
  Top Layer w0.18: RA33.3@153.247,74.148 153.247,74.866 153.089,75.024 153.089,77.051 153.257,77.219 M1.D06@153.257,78.1
CTRL_WAKE1_MICO#JMP: J7.14 J7B.7 | length 5.1
  Bottom Layer w0.15: J7B.7@52.68,102.12 J7.14@57.76,102.12
CYP_N: J65.A7 J65.B7 R321.2 | length 9.5
  Top Layer w0.15: J65.A7@27.75,192.622 27.825,192.697 27.825,193.22 v1(28.265,193.66) 28.675,193.25 28.675,192.697 J65.B7@28.75,192.622 ; v1(28.375,189.846) 28.375,189.759 28.15,189.533 28.15,189.163 28.238,189.075 28.325,189.075 28.75,188.65 R321.2@28.75,188.6 R321.2@28.75,188.588
  Bottom Layer w0.15: v1(28.265,193.66) 28.265,192.85 28.353,192.762 28.827,192.762 29.27,192.319 29.27,191.054 28.931,190.715 28.455,190.715 28.09,190.35 28.09,190.159 28.375,189.874 v1(28.375,189.846)
CYP_P: J65.A6 J65.B6 R320.2 | length 9.5
  Top Layer w0.15: R320.2@27.25,188.588 R320.2@27.25,188.6 27.25,188.65 27.675,189.075 27.762,189.075 27.85,189.163 27.85,189.482 27.505,189.827 v1(27.505,189.855) ; J65.B6@27.25,192.622 27.325,192.547 27.325,192.03 v1(27.77,191.585) 28.175,191.99 28.175,192.547 J65.A6@28.25,192.622
  Bottom Layer w0.15: v1(27.505,189.855) 27.505,189.883 27.79,190.168 27.79,190.474 28.331,191.015 28.807,191.015 28.97,191.178 28.97,191.399 28.726,191.643 28.726,191.768 28.97,192.012 28.97,192.195 28.702,192.462 28.251,192.462 27.856,192.067 27.856,191.671 v1(27.77,191.585)
D_1V8_LDO: C41.1 J63.1 U86.5 | length 69.3
  Top Layer w0.4: U86.5@41.25,178.809 42.664,178.809 C41.1@42.666,178.811 v1(42.666,179.837)
  Bottom Layer w0.3: v1(42.666,179.837) 36.85,174.021 36.85,163.225 35.814,162.189 35.814,160.733 42.343,154.204 58.195,154.204 63.6,148.799 63.6,144.741 60.629,141.77 J63.1@56.7,141.77
DFP_SSRX1_N: J72.B10 L95.4 U99.2 U99.9 | length 9
  Top Layer w0.15: v4(121.925,193.375) 121.925,193.458 122.105,193.638 122.105,193.887 122.075,193.917 122.075,194.175 J72.B10@122,194.25 ; v1(123.911,190.497) 123.911,190.409 124.135,190.184 124.135,189.405 124.035,189.305 124.035,188.93 124.135,188.83 124.135,188.571 124.035,188.471 124.035,188.096 124.147,187.984 124.147,187.313 124.125,187.291 124.125,187.2 L95.4@124.05,187.125
  Bottom Layer w0.15: v4(121.925,193.375) 121.925,193.312 122.125,193.112 122.125,192.779 122.564,192.34 123.268,192.34 124.136,191.472 124.136,191.015 124.14,191.01 124.14,190.81 123.911,190.58 v1(123.911,190.497)
DFP_SSRX1_P: J72.B11 L95.3 U99.1 U99.10 | length 9
  Top Layer w0.15: J72.B11@122.5,194.25 122.425,194.175 122.425,193.907 122.405,193.887 122.405,193.638 122.573,193.47 122.625,193.47 v4(122.625,193.375) ; L95.3@124.55,187.125 124.475,187.2 124.475,187.285 124.447,187.313 124.447,188.007 124.535,188.096 124.535,188.471 124.435,188.571 124.435,188.83 124.535,188.93 124.535,189.305 124.435,189.405 124.435,190.157 124.66,190.382 v1(124.66,190.47)
  Bottom Layer w0.15: v4(122.625,193.375) 122.625,193.312 122.425,193.112 122.425,192.904 122.689,192.64 123.392,192.64 124.436,191.596 124.436,191.139 124.44,191.134 124.44,190.783 124.66,190.563 v1(124.66,190.47)
DFP_SSRX2_N: J72.A10 L97.3 U98.1 U98.10 | length 5.7
  Top Layer w0.15: L97.3@118.15,187.125 118.075,187.2 118.075,187.288 118.05,187.313 118.05,187.996 118.15,188.096 U98.10@118.15,188.283 118.15,188.471 118.05,188.571 118.05,188.83 118.15,188.93 U98.1@118.15,189.117 118.15,189.305 118.05,189.405 118.05,190.809 118.15,190.909 118.15,192.187 118.175,192.212 118.175,192.475 J72.A10@118.25,192.55
DFP_SSRX2_P: J72.A11 L97.4 U98.2 U98.9 | length 5.7
  Top Layer w0.15: L97.4@117.65,187.125 117.725,187.2 117.725,187.288 117.75,187.313 117.75,187.996 117.65,188.096 U98.9@117.65,188.283 117.65,188.471 117.75,188.571 117.75,188.83 117.65,188.93 U98.2@117.65,189.117 117.65,189.305 117.75,189.405 117.75,190.933 117.85,191.034 117.85,192.187 117.825,192.212 117.825,192.475 J72.A11@117.75,192.55
DFP_SSTX1_N: J72.A3 L94.4 U99.5 U99.6 | length 6
  Top Layer w0.15: J72.A3@121.825,192.599 121.825,192.212 121.85,192.187 121.85,191.444 122.635,190.659 122.635,189.405 122.535,189.305 U99.5@122.535,189.117 122.535,188.93 122.635,188.83 122.635,188.571 122.535,188.471 122.535,188.096 122.627,188.004 122.627,187.313 122.6,187.286 122.6,187.2 L94.4@122.525,187.125
DFP_SSTX1_P: J72.A2 L94.3 U99.4 U99.7 | length 6
  Top Layer w0.15: J72.A2@122.25,192.55 122.175,192.475 122.175,192.212 122.15,192.187 122.15,191.568 122.935,190.783 122.935,189.405 123.035,189.305 U99.4@123.035,189.117 123.035,188.93 122.935,188.829 122.935,188.571 123.035,188.471 123.035,188.096 122.927,187.987 122.927,187.313 122.95,187.29 122.95,187.2 L94.3@123.025,187.125
DFP_SSTX2_N: J72.B3 L96.3 U98.4 U98.7 | length 9.1
  Top Layer w0.15: U98.4@116.562,189.377 116.562,190.003 116.566,190.006 116.566,190.351 116.795,190.581 v1(116.795,190.664) ; L96.3@116.65,187.125 116.575,187.2 116.575,187.288 116.55,187.313 116.55,187.996 116.65,188.096 U98.7@116.65,188.283 116.65,188.471 116.55,188.571 116.55,188.83 116.65,188.93 U98.4@116.65,189.117 ; J72.B3@118.5,194.25 118.425,194.175 118.425,193.916 118.396,193.887 118.396,193.613 118.6,193.409 v4(118.6,193.35)
  Bottom Layer w0.15: v1(116.795,190.664) 116.795,190.748 116.566,190.977 116.566,191.947 116.914,192.295 117.916,192.295 118.388,192.766 118.388,193.087 118.6,193.3 v4(118.6,193.35) 118.6,193.285 118.403,193.087
DFP_SSTX2_P: J72.B2 L96.4 U98.5 U98.6 | length 9.1
  Top Layer w0.15: v1(116.037,190.644) 116.037,190.56 116.266,190.331 116.266,190.131 116.263,190.127 U98.5@116.263,189.377 ; L96.4@116.15,187.125 116.225,187.2 116.225,187.288 116.25,187.313 116.25,187.995 116.15,188.096 U98.6@116.15,188.283 116.15,188.471 116.25,188.571 116.25,188.829 116.15,188.93 U98.5@116.15,189.117 ; v4(117.875,193.35) 117.875,193.392 118.096,193.613 118.096,193.887 118.075,193.908 118.075,194.175 J72.B2@118,194.25
  Bottom Layer w0.15: v1(116.037,190.644) 116.037,190.727 116.266,190.957 116.266,192.071 116.79,192.595 117.792,192.595 118.088,192.891 118.088,193.087 117.875,193.3 v4(117.875,193.35) 117.875,193.285 118.073,193.087
DMIC_CLK: R214.1 R297.1 U52.1 X75.1 | length 7
  Top Layer w0.15: X75.1@234.55,168.85 R214.1@234.55,170.75 R297.1@234.55,172.325 234.575,172.35 U52.1@238.071,172.35
DMIC_DATA: R192.1 R212.1 U52.25 X115.1 | length 6.7
  Top Layer w0.15: X115.1@234.55,179.25 234.55,177.4 R212.1@234.525,177.375 234.55,177.35 R192.1@234.55,175.675 235.708,175.675 235.858,175.825 236.542,175.825 236.692,175.675 U52.25@237.546,175.675
DP_1_AUX_N: L103.2 M1.A46 | length 146
  Top Layer w0.15: M1.A46@127.852,84.9 127.852,84.923 127.684,85.091 127.684,105.483 143.701,121.5 166.949,121.5 182.1,136.651 182.1,153.993 202.482,174.375 206.494,174.375 207.189,175.07 210.9,178.781 210.9,179.693 210.9,180.292 L103.2@211,180.392
DP_1_AUX_P: L103.1 M1.A47 | length 146
  Top Layer w0.15: M1.A47@127.217,84.9 127.217,84.923 127.384,85.091 127.384,105.608 143.576,121.8 166.825,121.8 181.8,136.775 181.8,154.117 202.358,174.675 206.37,174.675 210.6,178.905 210.6,180.292 L103.1@210.5,180.392
DP_1_HPD: J92.2 M1.B59 | length 185.2
  Top Layer w0.15: M1.B59@119.602,82.7 119.605,82.703 119.605,83.31 v1(119.608,83.314) ; v1(174.21,108.5) v1(209.485,108.5)
  Bottom Layer w0.15: v1(119.608,83.314) 120.046,83.314 121.337,84.604 122.906,84.604 123.432,85.131 123.432,87.551 129.752,93.87 140.712,93.87 151.024,104.182 151.024,111.938 152.206,113.12 170.737,113.12 174.21,109.647 v1(174.21,108.5) ; v1(209.485,108.5) 215.6,108.5 219.3,112.2 232.394,112.2 233.894,113.7 241.056,113.7 242.145,114.789 242.145,145.215 236.592,150.768 J92.2@236.592,151.02
DP_1_HPD_3V: J27.18 R270.1 U44.11 U47.4 U47.7 | length 72.8
  Top Layer w0.15: J27.18@211.75,186.427 211.75,185.07 212.125,184.695 212.125,183.842 212,183.717 U47.7@212,183.184 U47.4@212,182.35 212,182.038 212.05,181.988 R270.1@212.05,179.267 211.11,178.327 211.11,175.825 217.907,169.028 217.907,151.03 224.222,144.715 224.222,128.768 219.3,123.846 U44.11@219.3,121.725
DP_1_HPD_JMP: J92.1 RA10.4 U44.6 | length 71.3
  Top Layer w0.15: RA10.4@214.775,118.925 217.536,118.925 219.3,117.161 U44.6@219.3,115.525 219.3,113.903 220.078,113.125 241.584,113.125 v1(241.609,113.1)
  Bottom Layer w0.15: J92.1@239.132,151.02 243,147.152 243,114.491 v1(241.609,113.1)
DP_1_LANE0_N: L76.2 M1.A58 | length 146
  Top Layer w0.15: M1.A58@120.232,84.9 120.232,84.923 120.064,85.091 120.064,102.388 142.376,124.7 165.53,124.7 178.25,137.42 178.25,157.578 199.14,178.467 202.754,178.467 203.9,179.613 203.9,180.292 L76.2@204,180.392
DP_1_LANE0_P: L76.1 M1.A59 | length 146
  Top Layer w0.15: M1.A59@119.597,84.9 119.597,84.923 119.764,85.091 119.764,102.513 142.251,125 165.406,125 177.95,137.544 177.95,157.702 199.016,178.767 202.63,178.767 203.6,179.738 203.6,180.292 L76.1@203.5,180.392
DP_1_LANE1_N: L100.2 M1.A55 | length 146
  Top Layer w0.15: M1.A55@122.137,84.9 122.137,84.923 121.969,85.091 121.969,103.168 142.701,123.9 165.925,123.9 179.2,137.175 179.2,156.412 200.17,177.382 203.987,177.382 205.4,178.796 205.4,180.292 L100.2@205.5,180.392
DP_1_LANE1_P: L100.1 M1.A56 | length 146
  Top Layer w0.15: M1.A56@121.502,84.9 121.502,84.923 121.669,85.091 121.669,103.293 142.576,124.2 165.801,124.2 178.9,137.299 178.9,156.537 200.046,177.682 203.863,177.682 205.1,178.92 205.1,180.292 L100.1@205,180.392
DP_1_LANE2_N: L101.2 M1.A52 | length 146
  Top Layer w0.15: M1.A52@124.042,84.9 124.042,84.923 123.874,85.091 123.874,103.948 143.051,123.125 166.375,123.125 180.175,136.925 180.175,155.635 200.89,176.35 204.944,176.35 206.9,178.306 206.9,180.292 L101.2@207,180.392
DP_1_LANE2_P: L101.1 M1.A53 | length 146
  Top Layer w0.15: M1.A53@123.407,84.9 123.407,84.923 123.574,85.091 123.574,104.073 142.926,123.425 166.251,123.425 179.875,137.049 179.875,155.76 200.765,176.65 204.82,176.65 206.6,178.43 206.6,180.292 L101.1@206.5,180.392
DP_1_LANE3_N: L102.2 M1.A49 | length 146
  Top Layer w0.15: M1.A49@125.947,84.9 125.947,84.923 125.779,85.091 125.779,104.728 143.326,122.275 166.599,122.275 181.175,136.851 181.175,154.925 201.575,175.325 205.867,175.325 208.4,177.858 208.4,180.292 L102.2@208.5,180.392
DP_1_LANE3_P: L102.1 M1.A50 | length 146
  Top Layer w0.15: M1.A50@125.312,84.9 125.312,84.923 125.479,85.091 125.479,104.853 143.201,122.575 166.475,122.575 180.875,136.975 180.875,155.049 201.451,175.625 205.742,175.625 208.1,177.983 208.1,180.292 L102.1@208,180.392
DP_3V3: C345.2 C348.2 C349.2 C350.2 J27.20 R393.1 U47.5 U47.6 U80.6 X25.1 | length 16.3
  Top Layer w0.25: C345.2@212.835,181.267 212.5,181.602 U47.5@212.5,182.35 U47.6@212.5,183.184 212.5,184.117 212.75,184.367 J27.20@212.75,186.427 v1(213.327,186.427)
  Top Layer w0.5: C345.2@212.835,181.217 213.257,181.217 213.55,180.925 213.55,178.842 213.575,178.867 U80.6@216.995,178.867 217,178.862 X25.1@217,176.767
  Bottom Layer w0.25: R393.1@212.875,184.757 212.875,185.925 213.327,186.378 v1(213.327,186.427)
DP__1_AUX_N: J27.17 L103.3 R393.2 U47.2 U47.9 | length 6.5
  Top Layer w0.15: L103.3@211,181.043 210.925,181.117 210.925,181.205 210.9,181.23 210.9,182.07 211,182.17 U47.2@211,182.35 211,182.53 210.9,182.63 210.9,182.904 211,183.004 211,183.372 210.9,183.472 210.9,184.445 211.125,184.67 v1(211.125,184.757) 211.115,184.767 211.115,185.215 211.115,185.232 211.25,185.367 J27.17@211.25,186.427
  Bottom Layer w0.15: v1(211.125,184.757) R393.2@211.875,184.757
DP__1_AUX_P: J27.15 L103.4 R399.2 U47.1 U47.10 | length 6.5
  Top Layer w0.15: J27.15@210.25,186.427 210.25,185.367 210.385,185.232 210.385,184.767 v1(210.375,184.757) 210.375,184.67 210.6,184.445 210.6,183.464 210.5,183.364 210.5,183.004 210.6,182.904 210.6,182.631 210.5,182.53 210.5,182.17 210.6,182.07 210.6,181.23 210.575,181.205 210.575,181.117 L103.4@210.5,181.043
  Bottom Layer w0.15: R399.2@209.6,184.757 v1(210.375,184.757)
DP__1_LANE0_N: J27.3 L76.3 U46.2 U46.9 | length 5.7
  Top Layer w0.15: L76.3@204,181.043 203.925,181.117 203.925,181.205 203.9,181.23 203.9,182.07 204,182.17 U46.2@204,182.35 204,182.53 203.9,182.63 203.9,182.904 204,183.004 U46.9@204,183.184 204,183.364 203.9,183.464 203.9,184.068 203.9,184.919 204.115,185.134 204.115,185.232 204.25,185.367 J27.3@204.25,186.427
DP__1_LANE0_P: J27.1 L76.4 U46.1 U46.10 | length 5.7
  Top Layer w0.15: J27.1@203.25,186.427 203.25,185.367 203.385,185.232 203.385,185.134 203.6,184.919 203.6,183.943 203.6,183.464 203.5,183.364 U46.10@203.5,183.184 203.5,183.004 203.6,182.904 203.6,182.631 203.5,182.53 U46.1@203.5,182.35 203.5,182.17 203.6,182.07 203.6,181.23 203.575,181.205 203.575,181.117 L76.4@203.5,181.043
DP__1_LANE1_N: J27.6 L100.3 U46.5 U46.6 | length 5.7
  Top Layer w0.15: L100.3@205.5,181.043 205.425,181.117 205.425,181.205 205.4,181.23 205.4,182.07 205.5,182.17 U46.5@205.5,182.35 205.5,182.53 205.4,182.63 205.4,182.904 205.5,183.004 U46.6@205.5,183.184 205.5,183.364 205.4,183.464 205.4,184.068 205.4,184.919 205.615,185.134 205.615,185.232 205.75,185.367 J27.6@205.75,186.427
